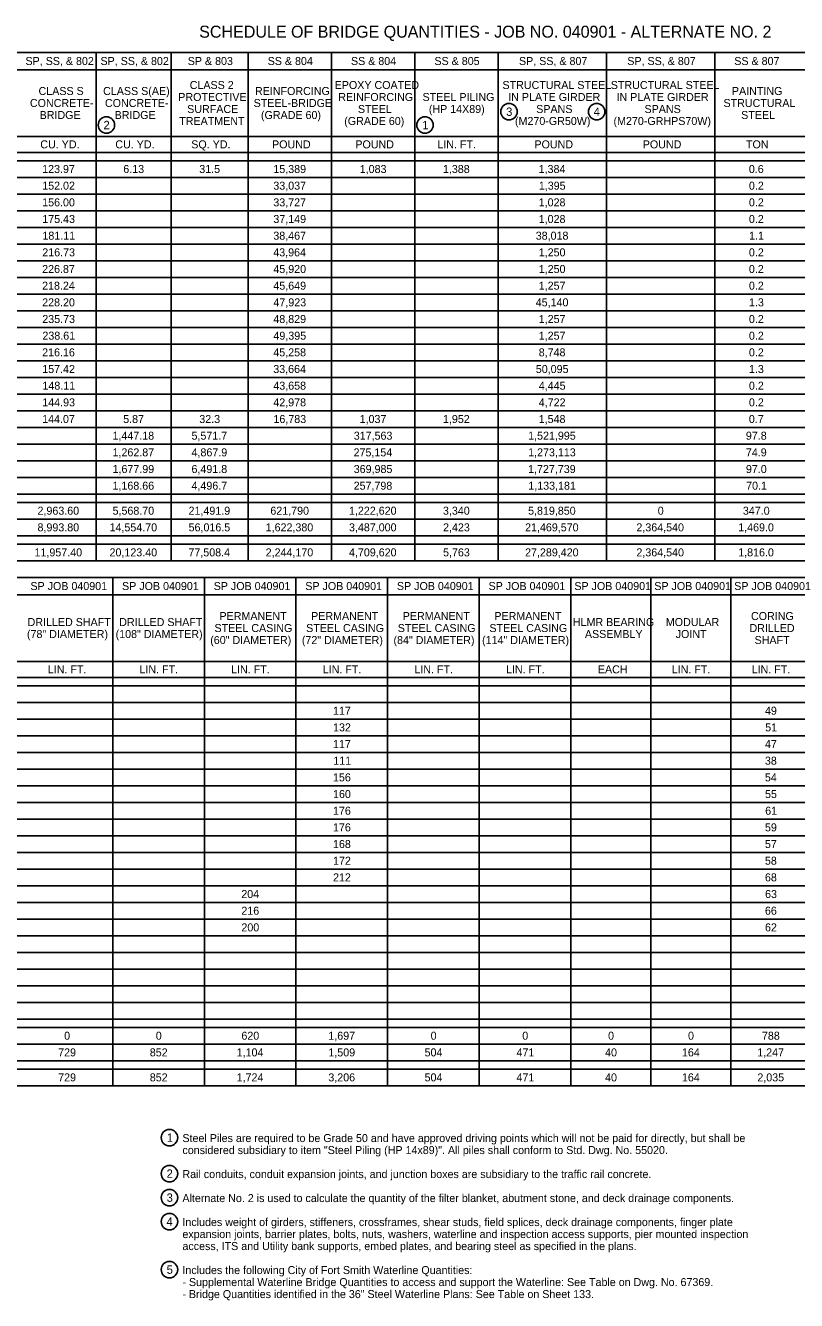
# Model space of a CAD drawing. Extents: x 0.06 to 1.36, y 0.04 to 0.85.
# Drawn here: x 0.423 to 0.905, y 0.057 to 0.854 of the extents above; entities that cross this region are included whole.
import ezdxf

# ---------------------------------------------------------------- set-up
doc = ezdxf.new("R2010")
doc.units = 0
for name, color, linetype in [('R_ROW', 7, 'Continuous'), ('R_Survey Control', 7, 'Continuous'), ('R_Wall', 7, 'Continuous')]:
    doc.layers.add(name, color=color, linetype=linetype)

msp = doc.modelspace()

# ---------------------------------------------------------------- linework, layer by layer
at = {"layer": 'R_Survey Control'}
for p, q in [((0.07508, 0.83695), (1.33392, 0.83695)), ((0.46733, 0.83695), (0.46733, 0.51924)), ((0.51421, 0.83695), (0.51421, 0.51924)), ((0.56236, 0.83695), (0.56236, 0.51924)), ((0.61444, 0.83695), (0.61444, 0.51924)), ((0.66653, 0.83695), (0.66653, 0.51924)), ((0.71861, 0.83695), (0.71861, 0.51924)), ((0.78632, 0.83695), (0.78632, 0.51924)), ((0.85407, 0.83695), (0.85407, 0.51924)), ((0.2593, 0.78445), (1.33392, 0.78445)), ((0.07508, 0.77445), (1.33392, 0.77445)), ((0.11154, 0.76924), (1.33392, 0.76924)), ((0.11154, 0.75883), (1.33392, 0.75883)), ((0.11154, 0.74841), (1.33392, 0.74841)), ((0.11154, 0.73799), (1.33392, 0.73799)), ((0.11154, 0.72758), (1.33392, 0.72758)), ((0.11154, 0.71716), (1.33392, 0.71716)), ((0.11154, 0.70674), (1.33392, 0.70674)), ((0.11154, 0.69633), (1.33392, 0.69633)), ((0.11154, 0.68591), (1.33392, 0.68591)), ((0.11154, 0.67549), (1.33392, 0.67549)), ((0.11154, 0.66508), (1.33392, 0.66508)), ((0.11154, 0.65466), (1.33392, 0.65466)), ((0.11154, 0.64424), (1.33392, 0.64424)), ((0.11154, 0.63383), (1.33392, 0.63383)), ((0.11154, 0.62341), (1.33392, 0.62341)), ((0.11154, 0.61299), (1.33392, 0.61299)), ((0.11154, 0.60258), (1.33392, 0.60258)), ((0.11154, 0.59216), (1.33392, 0.59216)), ((0.11154, 0.58174), (1.33392, 0.58174)), ((0.11154, 0.57133), (1.33392, 0.57133)), ((0.11154, 0.56091), (1.33392, 0.56091)), ((0.07508, 0.5557), (1.33392, 0.5557)), ((0.07508, 0.54529), (1.33392, 0.54529)), ((0.07508, 0.53487), (1.33392, 0.53487)), ((0.07508, 0.52966), (1.33392, 0.52966)), ((0.07508, 0.51924), (1.33392, 0.51924)), ((0.07508, 0.50883), (1.30054, 0.50883)), ((0.47769, 0.50883), (0.47769, 0.19112)), ((0.53498, 0.50883), (0.53498, 0.19112)), ((0.59227, 0.50883), (0.59227, 0.19112)), ((0.64957, 0.50883), (0.64957, 0.19112)), ((0.70686, 0.50883), (0.70686, 0.19112)), ((0.76415, 0.50883), (0.76415, 0.19112)), ((0.81414, 0.50883), (0.81414, 0.19112)), ((0.86412, 0.50883), (0.86412, 0.19112)), ((0.2593, 0.45633), (1.30054, 0.45633)), ((0.07508, 0.44633), (1.30054, 0.44633)), ((0.11154, 0.44112), (1.30054, 0.44112)), ((0.11154, 0.4307), (1.30054, 0.4307)), ((0.11154, 0.42029), (1.30054, 0.42029)), ((0.11154, 0.40987), (1.30054, 0.40987)), ((0.11154, 0.39945), (1.30054, 0.39945)), ((0.11154, 0.38904), (1.30054, 0.38904)), ((0.11154, 0.37862), (1.30054, 0.37862)), ((0.11154, 0.3682), (1.30054, 0.3682)), ((0.11154, 0.35779), (1.30054, 0.35779)), ((0.11154, 0.34737), (1.30054, 0.34737)), ((0.11154, 0.33695), (1.30054, 0.33695)), ((0.11154, 0.32654), (1.30054, 0.32654)), ((0.11154, 0.31612), (1.30054, 0.31612)), ((0.11154, 0.3057), (1.30054, 0.3057)), ((0.11154, 0.29529), (1.30054, 0.29529)), ((0.11154, 0.28487), (1.30054, 0.28487)), ((0.11154, 0.27445), (1.30054, 0.27445)), ((0.11154, 0.26404), (1.30054, 0.26404)), ((0.11154, 0.25362), (1.30054, 0.25362)), ((0.11154, 0.2432), (1.30054, 0.2432)), ((0.11154, 0.23279), (1.30054, 0.23279)), ((0.07508, 0.22758), (1.30054, 0.22758)), ((0.07508, 0.21716), (1.30054, 0.21716)), ((0.07508, 0.20674), (1.30054, 0.20674)), ((0.07508, 0.20154), (1.30054, 0.20154)), ((0.07508, 0.19112), (1.30054, 0.19112))]:
    msp.add_line(p, q, dxfattribs=at)
for points in [[(0.2593, 0.82612), (0.30425, 0.82612), (0.41883, 0.82612), (0.46733, 0.82612), (0.509, 0.82612), (0.55587, 0.82612), (0.59233, 0.82612), (0.6366, 0.82612), (0.68087, 0.82612), (0.74858, 0.82612), (0.79433, 0.82612), (0.84642, 0.82612), (0.94537, 0.82612), (1.00267, 0.82612), (1.06517, 0.82612), (1.19277, 0.82612), (1.26048, 0.82612), (1.31256, 0.82612), (1.33392, 0.82612)], [(0.2593, 0.49799), (0.30425, 0.49799), (0.36154, 0.49799), (0.40321, 0.49799), (0.44487, 0.49799), (0.49175, 0.49799), (0.52821, 0.49799), (0.58029, 0.49799), (0.64019, 0.49799), (0.7079, 0.49799), (0.75998, 0.49799), (0.81206, 0.49799), (0.85894, 0.49799), (0.86623, 0.49799), (0.92873, 0.49799), (0.99644, 0.49799), (1.06415, 0.49799), (1.11623, 0.49799), (1.16831, 0.49799), (1.30054, 0.49799)]]:
    msp.add_lwpolyline(points, dxfattribs=at)
at = {"layer": 'R_Wall'}
for centre in [(0.72543, 0.79986), (0.78027, 0.79986), (0.47374, 0.79152), (0.67293, 0.79152), (0.51317, 0.15868), (0.51317, 0.13618), (0.51317, 0.12118), (0.51317, 0.10618), (0.51317, 0.07618)]:
    msp.add_circle(centre, 0.00515, dxfattribs=at)

# ---------------------------------------------------------------- texts
at = {"layer": 'R_ROW'}
msp.add_text('SCHEDULE OF BRIDGE QUANTITIES - JOB NO. 040901 - ALTERNATE NO. 2', height=0.0075, dxfattribs=at).set_placement((0.53175, 0.84612))
at = {"layer": 'R_Survey Control'}
for s, p in [('SP, SS, & 802', (0.42313, 0.82904)), ('SP, SS, & 802', (0.47003, 0.82904)), ('SP & 803', (0.52458, 0.82904)), ('SS & 804', (0.57457, 0.82904)), ('SS & 804', (0.62665, 0.82904)), ('SS & 805', (0.67883, 0.82904)), ('SP, SS, & 807', (0.7317, 0.82904)), ('SP, SS, & 807', (0.79943, 0.82904)), ('SS & 807', (0.86631, 0.82904)), ('CLASS S ', (0.4313, 0.81029)), ('CLASS S(AE)', (0.47167, 0.81029)), ('CLASS 2', (0.52582, 0.81404)), ('REINFORCING', (0.56663, 0.81029)), ('EPOXY COATED', (0.61645, 0.81404)), ('STRUCTURAL STEEL', (0.72137, 0.81404)), ('STRUCTURAL STEEL', (0.78909, 0.81404)), ('PAINTING', (0.86485, 0.81029)), ('CONCRETE-', (0.42591, 0.80279)), ('CONCRETE-', (0.47282, 0.80279)), ('PROTECTIVE', (0.51866, 0.80654)), ('STEEL-BRIDGE', (0.56578, 0.80279)), ('REINFORCING', (0.61871, 0.80654)), ('STEEL PILING', (0.67141, 0.80654)), ('IN PLATE GIRDER', (0.72497, 0.80654)), ('IN PLATE GIRDER', (0.7927, 0.80654)), ('STRUCTURAL', (0.85957, 0.80279)), ('BRIDGE', (0.43198, 0.79529)), ('BRIDGE', (0.47888, 0.79529)), ('SURFACE', (0.52424, 0.79904)), ('(GRADE 60)', (0.57037, 0.79529)), ('STEEL', (0.631, 0.79904)), ('(HP 14X89)', (0.67532, 0.79904)), ('SPANS', (0.74247, 0.79904)), ('SPANS', (0.81019, 0.79904)), ('STEEL', (0.87063, 0.79529)), ('TREATMENT', (0.51926, 0.79154)), ('(GRADE 60)', (0.62245, 0.79154)), ('(M270-GR50W)', (0.7292, 0.79154)), ('(M270-GRHPS70W)', (0.7908, 0.79154)), ('CU. YD.', (0.4324, 0.77695)), ('CU. YD.', (0.4793, 0.77695)), ('SQ. YD.', (0.52679, 0.77695)), ('POUND', (0.5773, 0.77695)), ('POUND', (0.62938, 0.77695)), ('LIN. FT.', (0.68065, 0.77695)), ('POUND', (0.74136, 0.77695)), ('POUND', (0.80909, 0.77695)), ('TON', (0.87363, 0.77695)), ('123.97', (0.43357, 0.76154)), ('6.13', (0.4843, 0.76154)), ('31.5', (0.53179, 0.76154)), ('15,389', (0.57812, 0.76154)), ('1,083', (0.63213, 0.76154)), ('1,388', (0.68415, 0.76154)), ('1,384', (0.744, 0.76154)), ('0.6', (0.87543, 0.76154)), ('152.02', (0.4336, 0.75112)), ('33,037', (0.5781, 0.75112)), ('1,395', (0.7441, 0.75112)), ('0.2', (0.87547, 0.75112)), ('156.00', (0.43358, 0.7407)), ('33,727', (0.5781, 0.7407)), ('1,028', (0.74404, 0.7407)), ('0.2', (0.87547, 0.7407)), ('175.43', (0.43364, 0.73029)), ('37,149', (0.57812, 0.73029)), ('1,028', (0.74404, 0.73029)), ('0.2', (0.87547, 0.73029)), ('181.11', (0.43372, 0.71987)), ('38,467', (0.5781, 0.71987)), ('38,018', (0.74217, 0.71987)), ('1.1', (0.87559, 0.71987)), ('216.73', (0.43364, 0.70945)), ('43,964', (0.57806, 0.70945)), ('1,250', (0.74406, 0.70945)), ('0.2', (0.87547, 0.70945)), ('226.87', (0.43357, 0.69904)), ('45,920', (0.57812, 0.69904)), ('1,250', (0.74406, 0.69904)), ('0.2', (0.87547, 0.69904)), ('218.24', (0.43353, 0.68862)), ('45,649', (0.57812, 0.68862)), ('1,257', (0.74404, 0.68862)), ('0.2', (0.87547, 0.68862)), ('228.20', (0.43358, 0.6782)), ('47,923', (0.57817, 0.6782)), ('45,140', (0.74218, 0.6782)), ('1.3', (0.87551, 0.6782)), ('235.73', (0.43364, 0.66779)), ('48,829', (0.57812, 0.66779)), ('1,257', (0.74404, 0.66779)), ('0.2', (0.87547, 0.66779)), ('238.61', (0.43372, 0.65737)), ('49,395', (0.57816, 0.65737)), ('1,257', (0.74404, 0.65737)), ('0.2', (0.87547, 0.65737)), ('216.16', (0.43356, 0.64695)), ('45,258', (0.5781, 0.64695)), ('8,748', (0.74404, 0.64695)), ('0.2', (0.87547, 0.64695)), ('157.42', (0.4336, 0.63654)), ('33,664', (0.57806, 0.63654)), ('50,095', (0.74222, 0.63654)), ('1.3', (0.87551, 0.63654)), ('148.11', (0.43372, 0.62612)), ('43,658', (0.5781, 0.62612)), ('4,445', (0.7441, 0.62612)), ('0.2', (0.87547, 0.62612)), ('144.93', (0.43364, 0.6157)), ('42,978', (0.5781, 0.6157)), ('4,722', (0.74407, 0.6157)), ('0.2', (0.87547, 0.6157)), ('144.07', (0.43357, 0.60529)), ('5.87', (0.48422, 0.60529)), ('32.3', (0.53181, 0.60529)), ('16,783', (0.57817, 0.60529)), ('1,037', (0.63206, 0.60529)), ('1,952', (0.68417, 0.60529)), ('1,548', (0.74404, 0.60529)), ('0.7', (0.87544, 0.60529)), ('1,447.18', (0.47756, 0.59487)), ('5,571.7', (0.52694, 0.59487)), ('317,563', (0.62838, 0.59487)), ('1,521,995', (0.73743, 0.59487)), ('97.8', (0.87356, 0.59487)), ('1,262.87', (0.47756, 0.58445)), ('4,867.9', (0.52696, 0.58445)), ('275,154', (0.62827, 0.58445)), ('1,273,113', (0.73744, 0.58445)), ('74.9', (0.87358, 0.58445)), ('1,677.99', (0.47757, 0.57404)), ('6,491.8', (0.52694, 0.57404)), ('369,985', (0.62837, 0.57404)), ('1,727,739', (0.73739, 0.57404)), ('97.0', (0.87358, 0.57404)), ('1,168.66', (0.47755, 0.56362)), ('4,496.7', (0.52694, 0.56362)), ('257,798', (0.62831, 0.56362)), ('1,133,181', (0.73753, 0.56362)), ('70.1', (0.87372, 0.56362)), ('2,963.60', (0.43066, 0.54799)), ('5,568.70', (0.47757, 0.54799)), ('21,491.9', (0.52509, 0.54799)), ('621,790', (0.57624, 0.54799)), ('1,222,620', (0.62541, 0.54799)), ('3,340', (0.68416, 0.54799)), ('5,819,850', (0.73739, 0.54799)), ('0', (0.81845, 0.54799)), ('347.0', (0.8717, 0.54799)), ('8,993.80', (0.43066, 0.53758)), ('14,554.70', (0.47569, 0.53758)), ('56,016.5', (0.52512, 0.53758)), ('1,622,380', (0.57332, 0.53758)), ('3,487,000', (0.62541, 0.53758)), ('2,423', (0.68422, 0.53758)), ('21,469,570', (0.73551, 0.53758)), ('2,364,540', (0.80512, 0.53758)), ('1,469.0', (0.86878, 0.53758)), ('11,957.40', (0.42879, 0.52195)), ('20,123.40', (0.47569, 0.52195)), ('77,508.4', (0.52503, 0.52195)), ('2,244,170', (0.57332, 0.52195)), ('4,709,620', (0.62541, 0.52195)), ('5,763', (0.68422, 0.52195)), ('27,289,420', (0.73551, 0.52195)), ('2,364,540', (0.80512, 0.52195)), ('1,816.0', (0.86878, 0.52195)), ('SP JOB 040901', (0.42622, 0.50091)), ('SP JOB 040901', (0.48351, 0.50091)), ('SP JOB 040901', (0.5408, 0.50091)), ('SP JOB 040901', (0.59809, 0.50091)), ('SP JOB 040901', (0.65538, 0.50091)), ('SP JOB 040901', (0.71267, 0.50091)), ('SP JOB 040901', (0.76631, 0.50091)), ('SP JOB 040901', (0.8163, 0.50091)), ('SP JOB 040901', (0.86628, 0.50091)), ('PERMANENT', (0.54443, 0.48216)), ('PERMANENT', (0.60172, 0.48216)), ('PERMANENT', (0.65901, 0.48216)), ('PERMANENT', (0.71631, 0.48216)), ('CORING', (0.87677, 0.48216)), ('DRILLED SHAFT', (0.42444, 0.47841)), ('DRILLED SHAFT', (0.48174, 0.47841)), ('STEEL CASING', (0.54131, 0.47466)), ('STEEL CASING', (0.59861, 0.47466)), ('STEEL CASING', (0.6559, 0.47466)), ('STEEL CASING', (0.71319, 0.47466)), ('HLMR BEARING', (0.76539, 0.47841)), ('MODULAR', (0.8235, 0.47841)), ('DRILLED', (0.87579, 0.47466)), ('(78" DIAMETER)', (0.42406, 0.47091)), ('(108" DIAMETER)', (0.47948, 0.47091)), ('(60" DIAMETER)', (0.53864, 0.46716)), ('(72" DIAMETER)', (0.59594, 0.46716)), ('(84" DIAMETER)', (0.65323, 0.46716)), ('(114" DIAMETER)', (0.70864, 0.46716)), ('ASSEMBLY', (0.77293, 0.47091)), ('JOINT', (0.82968, 0.47091)), ('SHAFT', (0.87901, 0.46716)), ('LIN. FT.', (0.43712, 0.44883)), ('LIN. FT.', (0.49441, 0.44883)), ('LIN. FT.', (0.55171, 0.44883)), ('LIN. FT.', (0.609, 0.44883)), ('LIN. FT.', (0.66629, 0.44883)), ('LIN. FT.', (0.72358, 0.44883)), ('EACH', (0.78102, 0.44883)), ('LIN. FT.', (0.82721, 0.44883)), ('LIN. FT.', (0.87718, 0.44883)), ('117', (0.61541, 0.42299)), ('49', (0.8855, 0.42299)), ('132', (0.61544, 0.41258)), ('51', (0.88564, 0.41258)), ('117', (0.61541, 0.40216)), ('47', (0.88548, 0.40216)), ('111', (0.61557, 0.39174)), ('38', (0.88548, 0.39174)), ('156', (0.6154, 0.38133)), ('54', (0.88545, 0.38133)), ('160', (0.61543, 0.37091)), ('55', (0.88554, 0.37091)), ('176', (0.6154, 0.36049)), ('61', (0.88564, 0.36049)), ('176', (0.6154, 0.35008)), ('59', (0.8855, 0.35008)), ('168', (0.61541, 0.33966)), ('57', (0.88548, 0.33966)), ('172', (0.61544, 0.32924)), ('58', (0.88548, 0.32924)), ('212', (0.61544, 0.31883)), ('68', (0.88548, 0.31883)), ('204', (0.55808, 0.30841)), ('63', (0.88556, 0.30841)), ('216', (0.55811, 0.29799)), ('66', (0.88547, 0.29799)), ('200', (0.55814, 0.28758)), ('62', (0.88551, 0.28758)), ('0', (0.44731, 0.21987)), ('0', (0.5046, 0.21987)), ('620', (0.55814, 0.21987)), ('1,697', (0.6125, 0.21987)), ('0', (0.67647, 0.21987)), ('0', (0.73376, 0.21987)), ('0', (0.7874, 0.21987)), ('0', (0.83739, 0.21987)), ('788', (0.88361, 0.21987)), ('729', (0.44356, 0.20945)), ('852', (0.50086, 0.20945)), ('1,104', (0.55517, 0.20945)), ('1,509', (0.61252, 0.20945)), ('504', (0.67267, 0.20945)), ('471', (0.73015, 0.20945)), ('40', (0.78553, 0.20945)), ('164', (0.83359, 0.20945)), ('1,247', (0.88069, 0.20945)), ('729', (0.44356, 0.19383)), ('852', (0.50086, 0.19383)), ('1,724', (0.55517, 0.19383)), ('3,206', (0.61249, 0.19383)), ('504', (0.67267, 0.19383)), ('471', (0.73015, 0.19383)), ('40', (0.78553, 0.19383)), ('164', (0.83359, 0.19383)), ('2,035', (0.88075, 0.19383))]:
    msp.add_text(s, height=0.005, dxfattribs=at).set_placement(p)
at = {"layer": 'R_Wall'}
for s, height, p in [('3', 0.00521, (0.72368, 0.79725)), ('4', 0.00521, (0.7784, 0.79725)), ('2', 0.00521, (0.47194, 0.78892)), ('1', 0.00521, (0.67127, 0.78892)), ('1', 0.00521, (0.51151, 0.15608)), ('Steel Piles are required to be Grade 50 and have approved driving points which will not be paid for directly, but shall be ', 0.005, (0.52126, 0.1559)), ('considered subsidiary to item "Steel Piling (HP 14x89)". All piles shall conform to Std. Dwg. No. 55020.', 0.005, (0.52126, 0.1484)), ('2', 0.00521, (0.51138, 0.13358)), ('Rail conduits, conduit expansion joints, and junction boxes are subsidiary to the traffic rail concrete.', 0.005, (0.52126, 0.1334)), ('3', 0.00521, (0.51142, 0.11858)), ('Alternate No. 2 is used to calculate the quantity of the filter blanket, abutment stone, and deck drainage components.', 0.005, (0.52126, 0.1184)), ('4', 0.00521, (0.51131, 0.10358)), ('Includes weight of girders, stiffeners, crossframes, shear studs, field splices, deck drainage components, finger plate ', 0.005, (0.52126, 0.1034)), ('expansion joints, barrier plates, bolts, nuts, washers, waterline and inspection access supports, pier mounted inspection ', 0.005, (0.52126, 0.0959)), ('access, ITS and Utility bank supports, embed plates, and bearing steel as specified in the plans.', 0.005, (0.52126, 0.0884)), ('5', 0.00521, (0.51141, 0.07358)), ('Includes the following City of Fort Smith Waterline Quantities:', 0.005, (0.52126, 0.0734)), ('- Supplemental Waterline Bridge Quantities to access and support the Waterline: See Table on Dwg. No. 67369.', 0.005, (0.52126, 0.0659)), ('- Bridge Quantities identified in the 36" Steel Waterline Plans: See Table on Sheet 133.', 0.005, (0.52126, 0.0584))]:
    msp.add_text(s, height=height, dxfattribs=at).set_placement(p)

doc.saveas('drawing.dxf')
